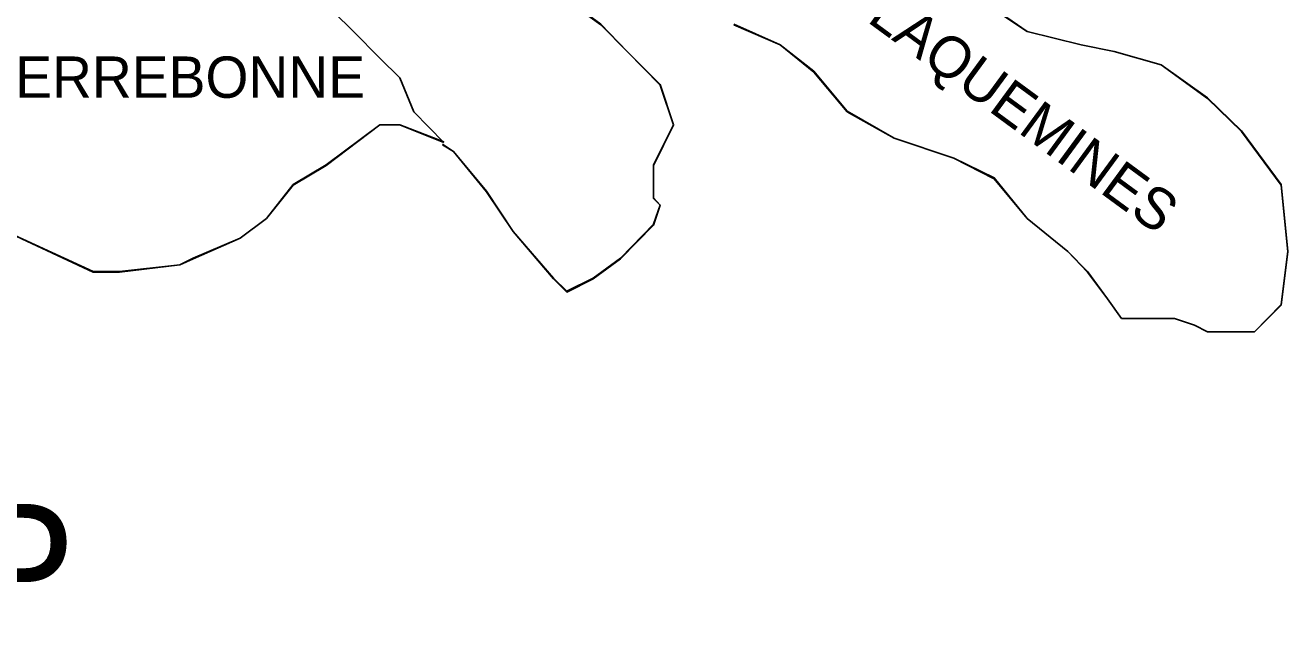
# Model space of a CAD drawing. Extents: x 0.19 to 2.82, y 0.04 to 1.79.
# Drawn here: x 2.4368 to 2.5798, y 1.3806 to 1.4495 of the extents above; entities that cross this region are included whole.
import ezdxf

# ---------------------------------------------------------------- set-up
doc = ezdxf.new("R2010")
doc.units = 0
doc.layers.add('Dist02', color=7, linetype='Continuous')
doc.layers.add('Standard Info', color=7, linetype='Continuous')

msp = doc.modelspace()

# ---------------------------------------------------------------- linework, layer by layer
at = {"layer": 'Dist02'}
for points in [[(2.48407, 1.43608), (2.48532, 1.43525), (2.48907, 1.43075), (2.49207, 1.42617), (2.49665, 1.42092), (2.49815, 1.41942), (2.50115, 1.42092), (2.50424, 1.42317), (2.50799, 1.427), (2.50874, 1.42917), (2.50799, 1.43), (2.50799, 1.43375), (2.51024, 1.43825), (2.50874, 1.44283), (2.50499, 1.44658), (2.50199, 1.44967), (2.4989, 1.45192), (2.4974, 1.45567)], [(2.51707, 1.44967), (2.52232, 1.44733), (2.52615, 1.44433), (2.5299, 1.43983), (2.53524, 1.43675), (2.54199, 1.4345), (2.54657, 1.43225), (2.55032, 1.42767), (2.5549, 1.42392), (2.55715, 1.42167), (2.5594, 1.41858), (2.56099, 1.41633), (2.56315, 1.41633), (2.56549, 1.41633), (2.56699, 1.41633), (2.56924, 1.41558), (2.57074, 1.41483), (2.57607, 1.41483), (2.57907, 1.41792), (2.57982, 1.42392), (2.57907, 1.4315), (2.57457, 1.43758), (2.57074, 1.44133), (2.56549, 1.44508), (2.56015, 1.44658), (2.5564, 1.44733), (2.55032, 1.44883), (2.54582, 1.45192)], [(2.41574, 1.43492), (2.41799, 1.43225), (2.42782, 1.4285), (2.43465, 1.42617), (2.44449, 1.42167), (2.44749, 1.42167), (2.45432, 1.42242), (2.45582, 1.42317), (2.46115, 1.42542), (2.46415, 1.42767), (2.46715, 1.4315), (2.4709, 1.43375), (2.47699, 1.43825), (2.47924, 1.43825), (2.48424, 1.43633)]]:
    msp.add_lwpolyline(points, dxfattribs=at)
at = {"layer": 'Standard Info'}
for points in [[(2.4369, 1.4685), (2.44599, 1.4685), (2.44599, 1.47075), (2.44899, 1.4715), (2.45057, 1.473), (2.45282, 1.4715), (2.45357, 1.47), (2.45507, 1.467), (2.45657, 1.46392), (2.46032, 1.46325), (2.46415, 1.46092), (2.4634, 1.45867), (2.46565, 1.45717), (2.4679, 1.45492), (2.4694, 1.45417), (2.47174, 1.45108), (2.47399, 1.44883), (2.47699, 1.44583), (2.47924, 1.44358), (2.48082, 1.43975), (2.48424, 1.43625)], [(2.48424, 1.43625), (2.48082, 1.43975), (2.47924, 1.44358), (2.47699, 1.44583), (2.47399, 1.44883), (2.47174, 1.45108), (2.4694, 1.45417), (2.4679, 1.45492), (2.46565, 1.45717), (2.4634, 1.45867), (2.46415, 1.46092), (2.46032, 1.46325), (2.45657, 1.46392), (2.45507, 1.467), (2.45357, 1.47), (2.45282, 1.4715), (2.45057, 1.473), (2.44899, 1.4715), (2.44599, 1.47075), (2.44599, 1.4685), (2.4369, 1.4685)], [(2.4974, 1.45567), (2.4989, 1.45183), (2.50199, 1.44958), (2.50499, 1.44658), (2.50874, 1.44275), (2.51024, 1.43825), (2.50799, 1.43367), (2.50799, 1.42992), (2.50874, 1.42917), (2.50799, 1.42692), (2.50424, 1.42308), (2.50115, 1.42083), (2.49815, 1.41933), (2.49665, 1.42083), (2.49207, 1.42617), (2.48907, 1.43067), (2.48532, 1.43525), (2.48407, 1.436)], [(2.54582, 1.45183), (2.55032, 1.44883), (2.5564, 1.44733), (2.56015, 1.44658), (2.56549, 1.44508), (2.57074, 1.44125), (2.57457, 1.4375), (2.57907, 1.43142), (2.57982, 1.42392), (2.57907, 1.41783), (2.57607, 1.41483), (2.57074, 1.41483), (2.56924, 1.41558), (2.56699, 1.41633), (2.56549, 1.41633), (2.56315, 1.41633), (2.56099, 1.41633), (2.5594, 1.41858), (2.55715, 1.42158), (2.5549, 1.42392), (2.55032, 1.42767), (2.54657, 1.43217), (2.54199, 1.4345), (2.53524, 1.43675), (2.5299, 1.43975), (2.52615, 1.44425), (2.52232, 1.44733), (2.51707, 1.44958)], [(2.48424, 1.43625), (2.47924, 1.43825), (2.47699, 1.43825), (2.4709, 1.43367), (2.46715, 1.43142), (2.46415, 1.42767), (2.46115, 1.42542), (2.45582, 1.42308), (2.45432, 1.42242), (2.44749, 1.42158), (2.44449, 1.42158), (2.43465, 1.42617), (2.42782, 1.42842), (2.41799, 1.43217), (2.41574, 1.43492)]]:
    msp.add_lwpolyline(points, dxfattribs=at)

# ---------------------------------------------------------------- texts
msp.add_text('PLAQUEMINES', height=0.004679, rotation=323.7253, dxfattribs=at).set_placement((2.52868, 1.45249))
for s, height, p in [('TERREBONNE', 0.004679, (2.43184, 1.44133)), ('VICINITY MAP', 0.0145, (2.31323, 1.38084))]:
    msp.add_text(s, height=height, dxfattribs=at).set_placement(p)

doc.saveas('drawing.dxf')
